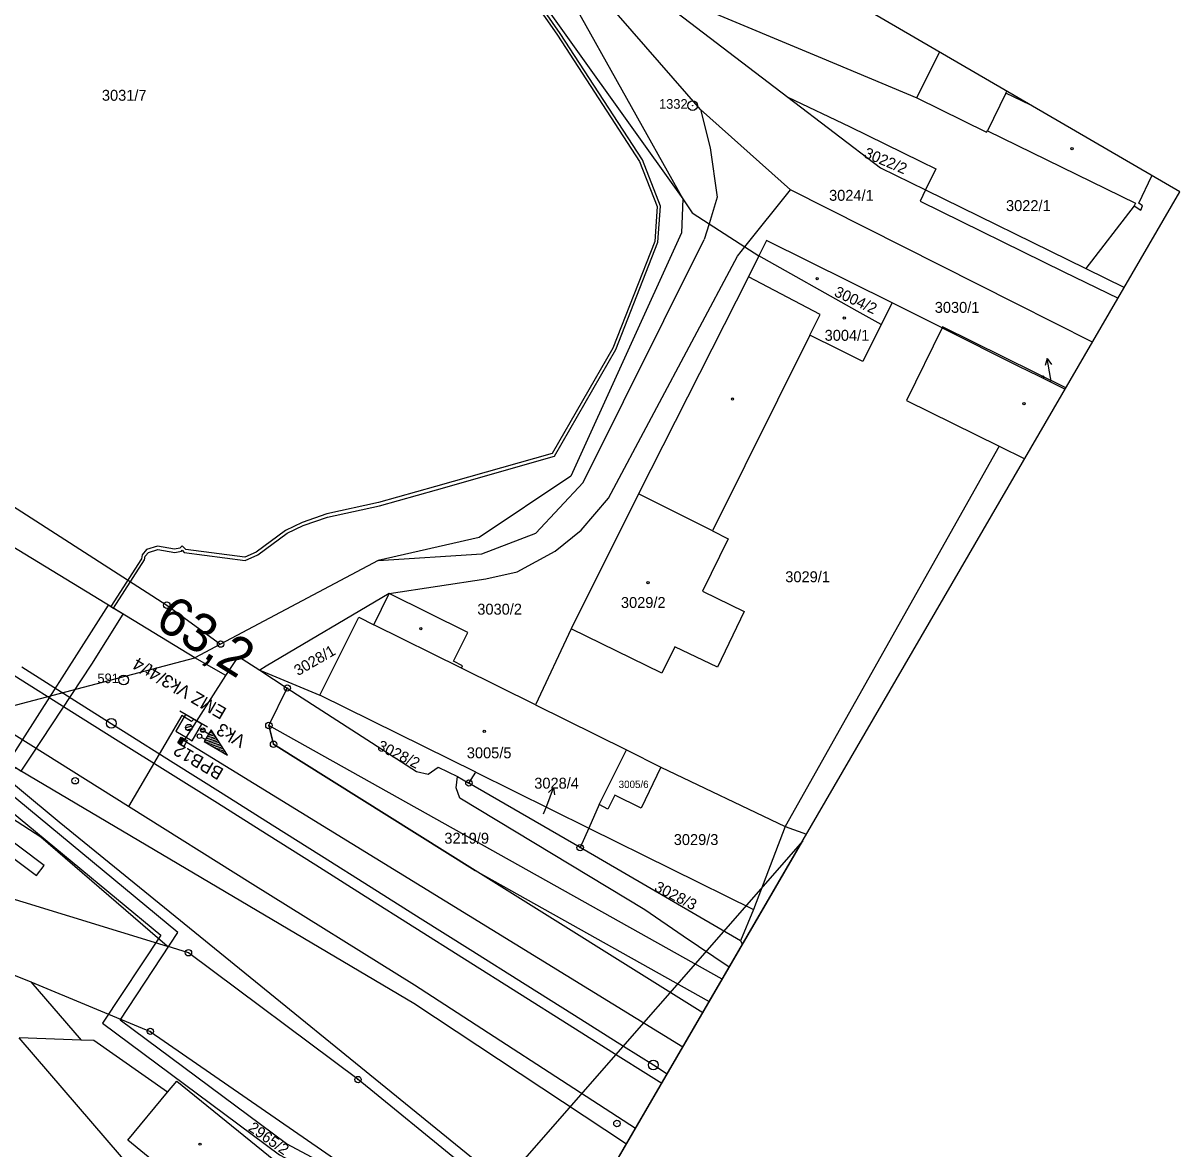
# Model space of a CAD drawing. Extents: x -621168 to -620292, y -1122748 to -1122069.
# Drawn here: x -620472.5 to -620292.4, y -1122640.4 to -1122465.1 of the extents above; entities that cross this region are included whole.
import ezdxf

# ---------------------------------------------------------------- set-up
doc = ezdxf.new("R2010")
doc.units = 0
for name, color, linetype in [('HranDP', 7, 'Continuous'), ('Hranice parcel', 7, 'Continuous'), ('Parcelní čísla', 7, 'Continuous'), ('Pop  PČ popisy', 7, 'Continuous'), ('Rámečky', 7, 'Continuous'), ('Rámečky-tisk', 7, 'Continuous'), ('Vnitřní kresba', 7, 'Continuous'), ('Vrstva 1', 7, 'Continuous'), ('Vrstva 14', 7, 'Continuous'), ('Vrstva 2', 7, 'Continuous'), ('Vrstva 3', 7, 'Continuous'), ('Vrstva 7', 7, 'Continuous'), ('Věcná břemena k části', 7, 'Continuous'), ('Značky bodu BP', 7, 'Continuous'), ('Značky budov', 7, 'Continuous')]:
    doc.layers.add(name, color=color, linetype=linetype)

msp = doc.modelspace()

# ---------------------------------------------------------------- linework, layer by layer
at = {"layer": 'HranDP'}
for p, q in [((-620445.8, -1122563.95), (-620552.09, -1122499.2)), ((-620440.98, -1122566.69), (-620445.8, -1122563.95)), ((-620435.69, -1122565.88), (-620431.39, -1122568.66))]:
    msp.add_line(p, q, dxfattribs=at)
for points in [[(-620440.98, -1122566.69), (-620438.97, -1122563.76), (-620435.69, -1122565.88)], [(-620366.69, -1122619.22), (-620402.13, -1122597.06), (-620433.53, -1122577.42), (-620434.26, -1122574.5), (-620431.39, -1122568.66)], [(-620378.58, -1122639.67), (-620411.71, -1122617.81), (-620485.21, -1122574.33)]]:
    msp.add_lwpolyline(points, dxfattribs=at)
at = {"layer": 'Hranice parcel'}
for p, q in [((-620396.46, -1122444.78), (-620369.79, -1122492.47)), ((-620379.27, -1122456.9), (-620353.42, -1122476.62)), ((-620331.97, -1122491.08), (-620307.02, -1122503.33)), ((-620445.8, -1122563.95), (-620552.09, -1122499.2)), ((-620356.75, -1122498.95), (-620357.94, -1122501.35)), ((-620337.18, -1122508.65), (-620356.75, -1122498.95)), ((-620357.94, -1122501.35), (-620359.58, -1122504.63)), ((-620307.02, -1122503.33), (-620301.01, -1122506.26)), ((-620359.58, -1122504.63), (-620376.68, -1122538.44)), ((-620337.18, -1122508.65), (-620338.89, -1122512.07)), ((-620329.41, -1122512.55), (-620337.18, -1122508.65)), ((-620320.51, -1122531), (-620353.86, -1122590.22)), ((-620320.51, -1122531), (-620316.53, -1122532.96)), ((-620376.68, -1122538.44), (-620387.17, -1122559.43)), ((-620365.17, -1122544.19), (-620376.68, -1122538.44)), ((-620387.17, -1122559.43), (-620392.72, -1122571.3)), ((-620441.78, -1122561.82), (-620445.8, -1122563.95)), ((-620440.98, -1122566.69), (-620445.8, -1122563.95)), ((-620435.69, -1122565.88), (-620426.32, -1122569.77)), ((-620435.69, -1122565.88), (-620431.39, -1122568.66)), ((-620402.04, -1122581.77), (-620426.32, -1122569.77)), ((-620392.72, -1122571.3), (-620378.57, -1122578.31)), ((-620382.82, -1122586.79), (-620378.57, -1122578.31)), ((-620378.57, -1122578.31), (-620373.23, -1122580.96)), ((-620373.23, -1122580.96), (-620353.86, -1122590.22)), ((-620403.1, -1122583.45), (-620402.04, -1122581.77)), ((-620402.04, -1122581.77), (-620384.45, -1122590.46)), ((-620385.78, -1122593.52), (-620403.1, -1122583.45)), ((-620382.82, -1122586.79), (-620384.45, -1122590.46)), ((-620353.86, -1122590.22), (-620358.78, -1122603.15)), ((-620353.86, -1122590.22), (-620350.53, -1122591.43)), ((-620384.45, -1122590.46), (-620385.78, -1122593.52)), ((-620384.45, -1122590.46), (-620358.78, -1122603.15)), ((-620360.83, -1122608.03), (-620385.78, -1122593.52)), ((-620358.78, -1122603.15), (-620360.83, -1122608.03)), ((-620360.83, -1122608.03), (-620360.52, -1122608.61)), ((-620446.79, -1122609.88), (-620450.13, -1122608.86))]:
    msp.add_line(p, q, dxfattribs=at)
for points in [[(-620476.11, -1122384.57), (-620448.57, -1122406.53), (-620412.63, -1122432.52), (-620369.79, -1122492.47)], [(-620353.03, -1122491.08), (-620367.06, -1122478.57), (-620396.46, -1122444.78)], [(-620379.27, -1122456.9), (-620367.13, -1122462.61), (-620348.06, -1122470.58), (-620333.32, -1122476.77)], [(-620333.32, -1122476.77), (-620329.82, -1122469.63)], [(-620353.42, -1122476.62), (-620343.83, -1122481.21), (-620332.72, -1122486.65), (-620330.38, -1122487.78), (-620331.97, -1122491.08)], [(-620353.42, -1122476.62), (-620338.98, -1122487.64), (-620331.97, -1122491.08)], [(-620333.32, -1122476.77), (-620322.48, -1122482.07), (-620322.35, -1122481.87), (-620299.27, -1122493.16), (-620299.47, -1122493.58), (-620307.02, -1122503.33)], [(-620305.98, -1122514.82), (-620317.91, -1122508.79), (-620353.03, -1122491.08)], [(-620331.97, -1122491.08), (-620332.81, -1122492.83), (-620310.42, -1122503.82), (-620301.99, -1122507.95)], [(-620369.79, -1122492.47), (-620370.01, -1122497.77), (-620387.25, -1122535.69), (-620401.53, -1122545.24), (-620417.25, -1122548.82), (-620441.78, -1122561.82)], [(-620369.79, -1122492.47), (-620368.34, -1122494.64), (-620365.69, -1122496.35), (-620360.13, -1122499.94), (-620357.94, -1122501.35)], [(-620338.89, -1122512.07), (-620342.65, -1122509.95), (-620357.94, -1122501.35)], [(-620338.89, -1122512.07), (-620341.77, -1122517.82), (-620345.51, -1122515.94), (-620349.99, -1122513.69), (-620365.17, -1122544.19)], [(-620329.41, -1122512.55), (-620334.96, -1122523.89), (-620320.51, -1122531)], [(-620310.11, -1122521.92), (-620329.34, -1122512.4), (-620329.41, -1122512.55)], [(-620329.41, -1122512.55), (-620317.53, -1122518.52), (-620314.41, -1122520.05), (-620310.23, -1122522.12)], [(-620475.79, -1122539.24), (-620450.17, -1122555.76), (-620441.78, -1122561.82)], [(-620365.17, -1122544.19), (-620362.75, -1122545.4), (-620366.73, -1122553.56), (-620360.24, -1122556.72), (-620364.41, -1122565.4), (-620371.05, -1122562.22), (-620373.07, -1122566.34), (-620387.17, -1122559.43)], [(-620415.52, -1122553.94), (-620434.68, -1122565.28), (-620435.69, -1122565.88)], [(-620426.32, -1122569.77), (-620420.27, -1122557.63), (-620417.91, -1122558.83), (-620415.52, -1122553.94)], [(-620392.72, -1122571.3), (-620404.28, -1122565.56), (-620404.12, -1122565.22), (-620405.52, -1122564.49), (-620403.26, -1122560.03), (-620415.52, -1122553.94)], [(-620440.98, -1122566.69), (-620438.97, -1122563.76), (-620435.69, -1122565.88)], [(-620369.81, -1122624.58), (-620447.48, -1122576.88), (-620440.98, -1122566.69)], [(-620366.69, -1122619.22), (-620402.13, -1122597.06), (-620433.53, -1122577.42), (-620434.26, -1122574.5), (-620431.39, -1122568.66)], [(-620431.39, -1122568.66), (-620411.27, -1122581.65), (-620409.46, -1122582.07), (-620407.91, -1122580.98), (-620404.87, -1122582.42), (-620403.1, -1122583.45)], [(-620485.21, -1122574.33), (-620466.94, -1122589.51), (-620387.14, -1122654.39)], [(-620378.58, -1122639.67), (-620411.71, -1122617.81), (-620485.21, -1122574.33)], [(-620450.13, -1122608.86), (-620469.8, -1122591.86), (-620494.61, -1122575.85)], [(-620373.23, -1122580.96), (-620376.29, -1122587.36), (-620380.38, -1122585.36), (-620381.45, -1122587.52), (-620382.82, -1122586.79)], [(-620482.88, -1122598.82), (-620472.56, -1122601.98), (-620450.13, -1122608.86)], [(-620388.08, -1122656.01), (-620420.38, -1122629.64), (-620446.79, -1122609.88)], [(-620478.83, -1122611.96), (-620474.31, -1122613.21), (-620471.33, -1122614.44), (-620452.73, -1122622.13)], [(-620452.73, -1122622.13), (-620423.22, -1122642.55), (-620404.9, -1122658.18), (-620395.68, -1122667.41), (-620395.02, -1122667.94)], [(-620450.04, -1122631.61), (-620461.53, -1122623.57), (-620463.51, -1122623.5), (-620473.14, -1122623.15)], [(-620410.99, -1122695.4), (-620434.88, -1122667.63), (-620473.14, -1122623.15)], [(-620450.04, -1122631.61), (-620448.58, -1122629.86), (-620432.38, -1122643.03)], [(-620432.38, -1122643.03), (-620440.08, -1122652.3), (-620456.23, -1122639.05), (-620450.04, -1122631.61)]]:
    msp.add_lwpolyline(points, dxfattribs=at)
at = {"layer": 'Pop  PČ popisy'}
for p, q in [((-620313.04, -1122517.36), (-620313.36, -1122518.44)), ((-620312.52, -1122520.32), (-620313.04, -1122517.36)), ((-620313.04, -1122517.36), (-620312.37, -1122518.26)), ((-620312.43, -1122520.86), (-620312.52, -1122520.32)), ((-620390.98, -1122586.98), (-620389.91, -1122584.18)), ((-620389.91, -1122584.18), (-620390.73, -1122584.93)), ((-620389.91, -1122584.18), (-620389.8, -1122585.29)), ((-620391.48, -1122588.26), (-620390.98, -1122586.98))]:
    msp.add_line(p, q, dxfattribs=at)
at = {"layer": 'Rámečky'}
msp.add_line((-620351.12, -1122592.44), (-620471.94, -1122730.56), dxfattribs=at)
msp.add_lwpolyline([(-620471.94, -1122730.56), (-620441.66, -1122748.16), (-620351.12, -1122592.44)], dxfattribs=at)
at = {"layer": 'Rámečky-tisk'}
msp.add_line((-620351.12, -1122592.44), (-620471.94, -1122730.56), dxfattribs=at)
for points in [[(-620441.66, -1122748.16), (-620292.37, -1122491.41), (-621018.54, -1122069.17)], [(-620471.94, -1122730.56), (-620441.66, -1122748.16), (-620351.12, -1122592.44)]]:
    msp.add_lwpolyline(points, dxfattribs=at)
at = {"layer": 'Vnitřní kresba'}
for p, q in [((-620319.48, -1122476.02), (-620322.35, -1122481.87)), ((-620319.48, -1122476.02), (-620319.34, -1122475.73)), ((-620315.59, -1122477.9), (-620319.48, -1122476.02)), ((-620367.06, -1122478.57), (-620365.53, -1122484.54)), ((-620365.53, -1122484.54), (-620364.42, -1122492.19)), ((-620298.76, -1122493.15), (-620296.74, -1122488.87)), ((-620360.13, -1122499.94), (-620353.03, -1122491.08)), ((-620364.42, -1122492.19), (-620365.69, -1122496.35)), ((-620299.47, -1122493.58), (-620298.47, -1122494.23)), ((-620298.2, -1122493.59), (-620298.76, -1122493.15)), ((-620298.47, -1122494.23), (-620298.2, -1122493.59)), ((-620365.69, -1122496.35), (-620366.44, -1122498.8)), ((-620385.3, -1122536.65), (-620366.44, -1122498.8)), ((-620361.28, -1122501.38), (-620360.13, -1122499.94)), ((-620381.37, -1122539.08), (-620361.28, -1122501.38)), ((-620348.39, -1122510.47), (-620359.58, -1122504.63)), ((-620349.99, -1122513.69), (-620348.39, -1122510.47)), ((-620392.7, -1122544.53), (-620385.3, -1122536.65)), ((-620385.63, -1122544.07), (-620381.37, -1122539.08)), ((-620401.09, -1122547.76), (-620392.7, -1122544.53)), ((-620389.68, -1122547.33), (-620385.63, -1122544.07)), ((-620417.25, -1122548.82), (-620401.09, -1122547.76)), ((-620395.61, -1122550.55), (-620389.68, -1122547.33)), ((-620400.46, -1122551.66), (-620395.61, -1122550.55)), ((-620415.52, -1122553.94), (-620400.46, -1122551.66)), ((-620404.28, -1122565.56), (-620417.91, -1122558.83)), ((-620485.21, -1122574.33), (-620445.8, -1122563.95)), ((-620405.1, -1122584.22), (-620404.87, -1122582.42)), ((-620404.53, -1122585.79), (-620405.1, -1122584.22)), ((-620375.73, -1122603.21), (-620404.53, -1122585.79)), ((-620369.73, -1122607.28), (-620375.73, -1122603.21)), ((-620362.58, -1122612.15), (-620369.73, -1122607.28)), ((-620471.33, -1122614.44), (-620463.51, -1122623.5))]:
    msp.add_line(p, q, dxfattribs=at)
at = {"layer": 'Vrstva 1'}
for p, q in [((-620447.82, -1122572.96), (-620456.11, -1122587.12)), ((-620446.31, -1122573.89), (-620447.82, -1122572.96)), ((-620445.97, -1122573.52), (-620446.31, -1122573.89))]:
    msp.add_line(p, q, dxfattribs=at)
for points in [[(-620456.11, -1122587.12), (-620500.01, -1122559.59), (-620522.22, -1122545.45), (-620544.95, -1122530.86)], [(-620472.76, -1122565.38), (-620464.48, -1122570.59), (-620458.81, -1122574.16), (-620456.89, -1122575.37), (-620449.16, -1122580.24), (-620441.4, -1122585.12), (-620433.76, -1122589.94), (-620426.06, -1122594.79), (-620418.33, -1122599.67), (-620410.68, -1122604.49), (-620402.92, -1122609.38), (-620394.33, -1122614.78), (-620386.67, -1122619.61), (-620379.01, -1122624.44), (-620374.38, -1122627.36), (-620372.22, -1122628.72)], [(-620447.82, -1122572.96), (-620447.82, -1122572.96), (-620447.82, -1122572.96), (-620447.82, -1122572.96), (-620447.82, -1122572.96)], [(-620377.18, -1122637.26), (-620411.56, -1122614.92), (-620436.76, -1122599.26), (-620456.11, -1122587.12)]]:
    msp.add_lwpolyline(points, dxfattribs=at)
at = {"layer": 'Vrstva 14'}
msp.add_lwpolyline([(-620510.69, -1122543.55), (-620509.04, -1122544.63), (-620501.84, -1122549.15), (-620491.85, -1122555.41), (-620483.32, -1122560.77), (-620478.25, -1122563.97), (-620473.97, -1122566.66), (-620465.4, -1122572.05), (-620457.72, -1122576.88), (-620450.01, -1122581.72), (-620442.29, -1122586.56), (-620434.63, -1122591.38), (-620426.95, -1122596.21), (-620419.24, -1122601.09), (-620411.54, -1122605.96), (-620403.8, -1122610.84), (-620395.25, -1122616.25), (-620387.51, -1122621.12), (-620379.87, -1122625.94), (-620375.57, -1122628.64), (-620373.08, -1122630.21)], dxfattribs=at)
at = {"layer": 'Vrstva 2'}
for p, q in [((-620447.27, -1122572.77), (-620448.78, -1122575.36)), ((-620443.81, -1122574.78), (-620448.14, -1122572.26)), ((-620444.68, -1122574.27), (-620447.27, -1122572.77)), ((-620448.78, -1122575.36), (-620446.19, -1122576.87)), ((-620446.28, -1122574.6), (-620447.22, -1122574.84)), ((-620446.27, -1122575.01), (-620447.03, -1122575.21)), ((-620446.19, -1122576.87), (-620444.68, -1122574.27)), ((-620447.66, -1122576.93), (-620448.38, -1122577.12)), ((-620447.75, -1122577.09), (-620448.38, -1122577.25)), ((-620447.57, -1122576.77), (-620448.28, -1122576.96)), ((-620447.85, -1122577.25), (-620448.22, -1122577.35)), ((-620447.47, -1122576.61), (-620448.19, -1122576.8)), ((-620447.59, -1122576.5), (-620448.1, -1122576.64)), ((-620447.94, -1122577.41), (-620448.06, -1122577.44)), ((-620447.75, -1122576.41), (-620448, -1122576.48))]:
    msp.add_line(p, q, dxfattribs=at)
for points in [[(-620447.98, -1122577.49), (-620448.44, -1122577.22), (-620447.91, -1122576.32), (-620447.46, -1122576.58)], [(-620447.98, -1122577.49), (-620448.44, -1122577.22), (-620447.91, -1122576.32), (-620447.46, -1122576.58)], [(-620447.53, -1122577.75), (-620448.44, -1122577.22), (-620447.91, -1122576.32), (-620447, -1122576.84)]]:
    msp.add_lwpolyline(points, close=True, dxfattribs=at)
msp.add_circle((-620446.73, -1122574.82), 0.5, dxfattribs=at)
at = {"layer": 'Vrstva 3'}
for p, q in [((-620444.89, -1122575.19), (-620444.27, -1122575.02)), ((-620444.82, -1122575.44), (-620444.2, -1122575.28)), ((-620444.4, -1122575.32), (-620443.63, -1122575.77)), ((-620443.73, -1122575.94), (-620442.9, -1122575.73)), ((-620443.54, -1122575.62), (-620443.06, -1122575.49)), ((-620443.36, -1122575.3), (-620443.21, -1122575.26)), ((-620444.15, -1122576.7), (-620444.75, -1122576.35)), ((-620444.29, -1122576.91), (-620442.45, -1122576.42)), ((-620444.1, -1122576.59), (-620442.6, -1122576.19)), ((-620444.08, -1122577.12), (-620442.3, -1122576.65)), ((-620443.92, -1122576.26), (-620442.75, -1122575.96)), ((-620443.76, -1122577.31), (-620442.15, -1122576.88)), ((-620443.44, -1122577.5), (-620441.99, -1122577.11)), ((-620443.12, -1122577.68), (-620441.84, -1122577.35)), ((-620442.79, -1122577.87), (-620441.69, -1122577.58)), ((-620442.47, -1122578.06), (-620441.54, -1122577.81)), ((-620442.15, -1122578.24), (-620441.39, -1122578.04)), ((-620441.83, -1122578.43), (-620441.23, -1122578.27)), ((-620441.51, -1122578.62), (-620441.08, -1122578.5)), ((-620441.19, -1122578.8), (-620440.93, -1122578.73)), ((-620440.87, -1122578.99), (-620440.78, -1122578.96))]:
    msp.add_line(p, q, dxfattribs=at)
msp.add_lwpolyline([(-620444.33, -1122576.98), (-620440.7, -1122579.09), (-620443.27, -1122575.16)], close=True, dxfattribs=at)
for centre in [(-620445.08, -1122576.15), (-620444.55, -1122575.23)]:
    msp.add_circle(centre, 0.35, dxfattribs=at)
at = {"layer": 'Vrstva 7'}
for p, q in [((-620464.48, -1122583.08), (-620464.39, -1122583.13)), ((-620380.09, -1122636.45), (-620380.01, -1122636.5))]:
    msp.add_line(p, q, dxfattribs=at)
for centre, radius in [((-620458.81, -1122574.16), 0.75), ((-620464.44, -1122583.1), 0.5), ((-620374.38, -1122627.36), 0.75), ((-620380.05, -1122636.48), 0.5)]:
    msp.add_circle(centre, radius, dxfattribs=at)
at = {"layer": 'Věcná břemena k části'}
msp.add_line((-620365.67, -1122617.46), (-620363.66, -1122614.01), dxfattribs=at)
for points in [[(-620399.94, -1122451.7), (-620389.31, -1122467), (-620376.53, -1122486.64), (-620373.78, -1122493.69), (-620374.17, -1122499.11), (-620380.7, -1122515.71), (-620390.13, -1122532.15), (-620408.3, -1122537.29), (-620417.17, -1122539.78), (-620425.25, -1122541.55), (-620429.09, -1122542.9), (-620431.68, -1122544.11), (-620436.23, -1122547.48), (-620438.03, -1122548.3), (-620447.21, -1122547.08), (-620447.75, -1122546.49), (-620448.13, -1122546.86), (-620448.94, -1122547.05), (-620451.62, -1122546.56), (-620453.33, -1122547.1), (-620454, -1122547.92), (-620454.09, -1122548.53), (-620458.89, -1122555.98), (-620458.46, -1122556.24), (-620453.61, -1122548.71), (-620453.52, -1122548.14), (-620453.03, -1122547.54), (-620451.58, -1122547.08), (-620448.92, -1122547.57), (-620447.89, -1122547.32), (-620447.77, -1122547.21), (-620447.45, -1122547.56), (-620437.95, -1122548.82), (-620435.97, -1122547.92), (-620431.42, -1122544.55), (-620428.91, -1122543.36), (-620425.11, -1122542.03), (-620417.05, -1122540.26), (-620408.16, -1122537.77), (-620389.79, -1122532.57), (-620380.24, -1122515.93), (-620373.67, -1122499.23), (-620373.28, -1122493.61), (-620376.09, -1122486.42), (-620388.89, -1122466.72), (-620399.52, -1122451.42)], [(-620363.66, -1122614.01), (-620434.26, -1122574.5), (-620433.53, -1122577.42), (-620402.13, -1122597.06), (-620365.67, -1122617.46)], [(-620394.32, -1122666.74), (-620417.42, -1122647.16), (-620431.52, -1122639.64), (-620457.44, -1122620.38), (-620448.45, -1122606.75), (-620478.4, -1122581.98), (-620488.36, -1122586.21), (-620487.32, -1122587.95), (-620478.74, -1122584.3), (-620451.11, -1122607.15), (-620460.16, -1122620.86), (-620432.6, -1122641.34), (-620418.54, -1122648.82), (-620395.34, -1122668.49)]]:
    msp.add_lwpolyline(points, dxfattribs=at)
for points in [[(-620456.96, -1122557.15), (-620459.28, -1122555.74), (-620474.94, -1122580.24), (-620474.78, -1122580.35), (-620474.85, -1122580.46), (-620473.73, -1122581.12), (-620473.69, -1122581.06), (-620472.83, -1122581.63), (-620471.16, -1122579.11), (-620461.86, -1122564.94)], [(-620481.88, -1122589.35), (-620470.44, -1122597.88), (-620469.24, -1122596.28), (-620480.68, -1122587.75)]]:
    msp.add_lwpolyline(points, close=True, dxfattribs=at)
at = {"layer": 'Značky bodu BP'}
for centre, radius in [((-620368.25, -1122477.95), 0.75), ((-620368.25, -1122477.95), 0.03), ((-620450.17, -1122555.76), 0.5), ((-620450.17, -1122555.76), 0.0303), ((-620441.78, -1122561.82), 0.5), ((-620441.78, -1122561.82), 0.0303), ((-620456.87, -1122567.4), 0.75), ((-620456.87, -1122567.4), 0.03), ((-620431.39, -1122568.66), 0.5), ((-620431.39, -1122568.66), 0.0303), ((-620434.26, -1122574.5), 0.5), ((-620434.26, -1122574.5), 0.0303), ((-620433.53, -1122577.42), 0.5), ((-620433.53, -1122577.42), 0.0303), ((-620403.1, -1122583.45), 0.5), ((-620403.1, -1122583.45), 0.0303), ((-620385.78, -1122593.52), 0.5), ((-620385.78, -1122593.52), 0.0303), ((-620446.79, -1122609.88), 0.5), ((-620446.79, -1122609.88), 0.0303), ((-620452.73, -1122622.13), 0.5), ((-620452.73, -1122622.13), 0.0303), ((-620420.38, -1122629.64), 0.5), ((-620420.38, -1122629.64), 0.0303)]:
    msp.add_circle(centre, radius, dxfattribs=at)
at = {"layer": 'Značky budov'}
for centre in [(-620309.17, -1122484.66), (-620348.86, -1122504.89), (-620344.65, -1122511.04), (-620313.72, -1122520.23), (-620362.05, -1122523.65), (-620316.66, -1122524.37), (-620375.21, -1122552.24), (-620410.6, -1122559.41), (-620400.72, -1122575.42), (-620444.99, -1122639.7)]:
    msp.add_circle(centre, 0.175, dxfattribs=at)

# ---------------------------------------------------------------- texts
at = {"layer": 'Parcelní čísla'}
for s, height, p in [('3031/7', 1.7, (-620460.27, -1122477.2)), ('3024/1', 1.7, (-620347.01, -1122492.78)), ('3022/1', 1.7, (-620319.45, -1122494.38)), ('3030/1', 1.7, (-620330.55, -1122510.23)), ('3004/1', 1.7, (-620347.7, -1122514.58)), ('3029/1', 1.7, (-620353.83, -1122552.18)), ('3030/2', 1.7, (-620401.8, -1122557.23)), ('3029/2', 1.7, (-620379.43, -1122556.19)), ('3005/5', 1.7, (-620403.43, -1122579.6)), ('3028/4', 1.7, (-620392.93, -1122584.33)), ('3005/6', 1.139, (-620379.78, -1122584.23)), ('3219/9', 1.7, (-620406.93, -1122592.9)), ('3029/3', 1.7, (-620371.2, -1122593.11))]:
    msp.add_text(s, height=height, dxfattribs=at).set_placement(p)
for s, rotation, p in [('3022/2', 337, (-620341.72, -1122485.96)), ('3004/2', 335, (-620346.35, -1122507.55)), ('3028/1', 30, (-620429.73, -1122566.82)), ('3028/2', 334, (-620417.52, -1122578.22)), ('3028/3', 333, (-620374.36, -1122600.16)), ('2965/2', 325, (-620437.6, -1122637.48))]:
    msp.add_text(s, height=1.7, rotation=rotation, dxfattribs=at).set_placement(p)
at = {"layer": 'Vrstva 3'}
for s, p in [('EMZ Vk3/4t/4', (-620440.69, -1122571.92)), ('Vk3', (-620437.67, -1122576.33)), ('BPB12', (-620441.14, -1122581.35))]:
    msp.add_text(s, height=2, rotation=149.8236, dxfattribs=at).set_placement(p)
at = {"layer": 'Vrstva 7'}
msp.add_text('63,2', height=6, rotation=327.8019, dxfattribs=at).set_placement((-620452.26, -1122558.96))
at = {"layer": 'Značky bodu BP'}
for s, p in [('1332', (-620373.5, -1122478.45)), ('591', (-620460.97, -1122567.9))]:
    msp.add_text(s, height=1.5, dxfattribs=at).set_placement(p)

doc.saveas('drawing.dxf')
